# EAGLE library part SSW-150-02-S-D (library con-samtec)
THROUGH-HOLE .025" SQ POST SOCKET Source: Samtec SSW.pdf
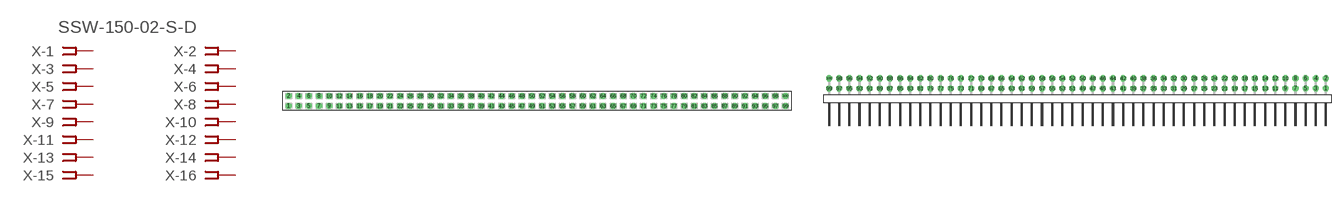
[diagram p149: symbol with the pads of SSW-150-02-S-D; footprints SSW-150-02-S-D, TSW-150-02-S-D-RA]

Designator prefix X; gates -1=FPINV -2=FPIN -3=FPIN -4=FPIN -5=FPIN -6=FPIN -7=FPIN -8=FPIN -9=FPIN -10=FPIN -11=FPIN -12=FPIN -13=FPIN -14=FPIN -15=FPIN -16=FPIN -17=FPIN -18=FPIN -19=FPIN -20=FPIN -21=FPIN -22=FPIN -23=FPIN -24=FPIN -25=FPIN -26=FPIN -27=FPIN -28=FPIN -29=FPIN -30=FPIN -31=FPIN -32=FPIN -33=FPIN -34=FPIN -35=FPIN -36=FPIN -37=FPIN -38=FPIN -39=FPIN -40=FPIN -41=FPIN -42=FPIN -43=FPIN -44=FPIN -45=FPIN -46=FPIN -47=FPIN -48=FPIN -49=FPIN -50=FPIN -51=FPIN -52=FPIN -53=FPIN -54=FPIN -55=FPIN -56=FPIN -57=FPIN -58=FPIN -59=FPIN -60=FPIN -61=FPIN -62=FPIN -63=FPIN -64=FPIN -65=FPIN -66=FPIN -67=FPIN -68=FPIN -69=FPIN -70=FPIN -71=FPIN -72=FPIN -73=FPIN -74=FPIN -75=FPIN -76=FPIN -77=FPIN -78=FPIN -79=FPIN -80=FPIN -81=FPIN -82=FPIN -83=FPIN -84=FPIN -85=FPIN -86=FPIN -87=FPIN -88=FPIN -89=FPIN -90=FPIN -91=FPIN -92=FPIN -93=FPIN -94=FPIN -95=FPIN -96=FPIN -97=FPIN -98=FPIN -99=FPIN -100=FPIN

## SSW-150-02-S-D (MPN: SSW-150-02-S-D; OC_FARNELL: unknown; OC_NEWARK: 12P0071)  [SSW-150-02-S-D]
1  -1:1  pas
2  -2:1  pas
3  -3:1  pas
4  -4:1  pas
5  -5:1  pas
6  -6:1  pas
7  -7:1  pas
8  -8:1  pas
9  -9:1  pas
10  -10:1  pas
11  -11:1  pas
12  -12:1  pas
13  -13:1  pas
14  -14:1  pas
15  -15:1  pas
16  -16:1  pas
17  -17:1  pas
18  -18:1  pas
19  -19:1  pas
20  -20:1  pas
21  -21:1  pas
22  -22:1  pas
23  -23:1  pas
24  -24:1  pas
25  -25:1  pas
26  -26:1  pas
27  -27:1  pas
28  -28:1  pas
29  -29:1  pas
30  -30:1  pas
31  -31:1  pas
32  -32:1  pas
33  -33:1  pas
34  -34:1  pas
35  -35:1  pas
36  -36:1  pas
37  -37:1  pas
38  -38:1  pas
39  -39:1  pas
40  -40:1  pas
41  -41:1  pas
42  -42:1  pas
43  -43:1  pas
44  -44:1  pas
45  -45:1  pas
46  -46:1  pas
47  -47:1  pas
48  -48:1  pas
49  -49:1  pas
50  -50:1  pas
51  -51:1  pas
52  -52:1  pas
53  -53:1  pas
54  -54:1  pas
55  -55:1  pas
56  -56:1  pas
57  -57:1  pas
58  -58:1  pas
59  -59:1  pas
60  -60:1  pas
61  -61:1  pas
62  -62:1  pas
63  -63:1  pas
64  -64:1  pas
65  -65:1  pas
66  -66:1  pas
67  -67:1  pas
68  -68:1  pas
69  -69:1  pas
70  -70:1  pas
71  -71:1  pas
72  -72:1  pas
73  -73:1  pas
74  -74:1  pas
75  -75:1  pas
76  -76:1  pas
77  -77:1  pas
78  -78:1  pas
79  -79:1  pas
80  -80:1  pas
81  -81:1  pas
82  -82:1  pas
83  -83:1  pas
84  -84:1  pas
85  -85:1  pas
86  -86:1  pas
87  -87:1  pas
88  -88:1  pas
89  -89:1  pas
90  -90:1  pas
91  -91:1  pas
92  -92:1  pas
93  -93:1  pas
94  -94:1  pas
95  -95:1  pas
96  -96:1  pas
97  -97:1  pas
98  -98:1  pas
99  -99:1  pas
100  -100:1  pas

## SSW-150-02-S-D-RA (MPN: SSW-150-02-S-D-RA; OC_FARNELL: unknown; OC_NEWARK: 12P0072)  [TSW-150-02-S-D-RA]
Pads as for SSW-150-02-S-D

## Footprint SSW-150-02-S-D (pad centres in mm)
THROUGH-HOLE .025" SQ POST SOCKET Source: Samtec SSW.pdf
drill 1 pad 1.5 octagon: 1 -62.23,-1.27; 2 -62.23,1.27; 3 -59.69,-1.27; 4 -59.69,1.27; 5 -57.15,-1.27; 6 -57.15,1.27; 7 -54.61,-1.27; 8 -54.61,1.27; 9 -52.07,-1.27; 10 -52.07,1.27; 11 -49.53,-1.27; 12 -49.53,1.27; 13 -46.99,-1.27; 14 -46.99,1.27; 15 -44.45,-1.27; 16 -44.45,1.27; 17 -41.91,-1.27; 18 -41.91,1.27; 19 -39.37,-1.27; 20 -39.37,1.27; 21 -36.83,-1.27; 22 -36.83,1.27; 23 -34.29,-1.27; 24 -34.29,1.27; 25 -31.75,-1.27; 26 -31.75,1.27; 27 -29.21,-1.27; 28 -29.21,1.27; 29 -26.67,-1.27; 30 -26.67,1.27; 31 -24.13,-1.27; 32 -24.13,1.27; 33 -21.59,-1.27; 34 -21.59,1.27; 35 -19.05,-1.27; 36 -19.05,1.27; 37 -16.51,-1.27; 38 -16.51,1.27; 39 -13.97,-1.27; 40 -13.97,1.27; 41 -11.43,-1.27; 42 -11.43,1.27; 43 -8.89,-1.27; 44 -8.89,1.27; 45 -6.35,-1.27; 46 -6.35,1.27; 47 -3.81,-1.27; 48 -3.81,1.27; 49 -1.27,-1.27; 50 -1.27,1.27; 51 1.27,-1.27; 52 1.27,1.27; 53 3.81,-1.27; 54 3.81,1.27; 55 6.35,-1.27; 56 6.35,1.27; 57 8.89,-1.27; 58 8.89,1.27; 59 11.43,-1.27; 60 11.43,1.27; 61 13.97,-1.27; 62 13.97,1.27; 63 16.51,-1.27; 64 16.51,1.27; 65 19.05,-1.27; 66 19.05,1.27; 67 21.59,-1.27; 68 21.59,1.27; 69 24.13,-1.27; 70 24.13,1.27; 71 26.67,-1.27; 72 26.67,1.27; 73 29.21,-1.27; 74 29.21,1.27; 75 31.75,-1.27; 76 31.75,1.27; 77 34.29,-1.27; 78 34.29,1.27; 79 36.83,-1.27; 80 36.83,1.27; 81 39.37,-1.27; 82 39.37,1.27; 83 41.91,-1.27; 84 41.91,1.27; 85 44.45,-1.27; 86 44.45,1.27; 87 46.99,-1.27; 88 46.99,1.27; 89 49.53,-1.27; 90 49.53,1.27; 91 52.07,-1.27; 92 52.07,1.27; 93 54.61,-1.27; 94 54.61,1.27; 95 57.15,-1.27; 96 57.15,1.27; 97 59.69,-1.27; 98 59.69,1.27; 99 62.23,-1.27; 100 62.23,1.27

## Footprint TSW-150-02-S-D-RA (pad centres in mm)
THROUGH-HOLE .025" SQ POST HEADER Source: Samtec TSW.pdf
drill 1 pad 1.5 octagon: 1 62.23,1.524; 2 62.23,4.064; 3 59.69,1.524; 4 59.69,4.064; 5 57.15,1.524; 6 57.15,4.064; 7 54.61,1.524; 8 54.61,4.064; 9 52.07,1.524; 10 52.07,4.064; 11 49.53,1.524; 12 49.53,4.064; 13 46.99,1.524; 14 46.99,4.064; 15 44.45,1.524; 16 44.45,4.064; 17 41.91,1.524; 18 41.91,4.064; 19 39.37,1.524; 20 39.37,4.064; 21 36.83,1.524; 22 36.83,4.064; 23 34.29,1.524; 24 34.29,4.064; 25 31.75,1.524; 26 31.75,4.064; 27 29.21,1.524; 28 29.21,4.064; 29 26.67,1.524; 30 26.67,4.064; 31 24.13,1.524; 32 24.13,4.064; 33 21.59,1.524; 34 21.59,4.064; 35 19.05,1.524; 36 19.05,4.064; 37 16.51,1.524; 38 16.51,4.064; 39 13.97,1.524; 40 13.97,4.064; 41 11.43,1.524; 42 11.43,4.064; 43 8.89,1.524; 44 8.89,4.064; 45 6.35,1.524; 46 6.35,4.064; 47 3.81,1.524; 48 3.81,4.064; 49 1.27,1.524; 50 1.27,4.064; 51 -1.27,1.524; 52 -1.27,4.064; 53 -3.81,1.524; 54 -3.81,4.064; 55 -6.35,1.524; 56 -6.35,4.064; 57 -8.89,1.524; 58 -8.89,4.064; 59 -11.43,1.524; 60 -11.43,4.064; 61 -13.97,1.524; 62 -13.97,4.064; 63 -16.51,1.524; 64 -16.51,4.064; 65 -19.05,1.524; 66 -19.05,4.064; 67 -21.59,1.524; 68 -21.59,4.064; 69 -24.13,1.524; 70 -24.13,4.064; 71 -26.67,1.524; 72 -26.67,4.064; 73 -29.21,1.524; 74 -29.21,4.064; 75 -31.75,1.524; 76 -31.75,4.064; 77 -34.29,1.524; 78 -34.29,4.064; 79 -36.83,1.524; 80 -36.83,4.064; 81 -39.37,1.524; 82 -39.37,4.064; 83 -41.91,1.524; 84 -41.91,4.064; 85 -44.45,1.524; 86 -44.45,4.064; 87 -46.99,1.524; 88 -46.99,4.064; 89 -49.53,1.524; 90 -49.53,4.064; 91 -52.07,1.524; 92 -52.07,4.064; 93 -54.61,1.524; 94 -54.61,4.064; 95 -57.15,1.524; 96 -57.15,4.064; 97 -59.69,1.524; 98 -59.69,4.064; 99 -62.23,1.524; 100 -62.23,4.064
